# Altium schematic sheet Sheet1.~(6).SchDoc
size A3; SheetNumber: 1; SheetTotal: 1
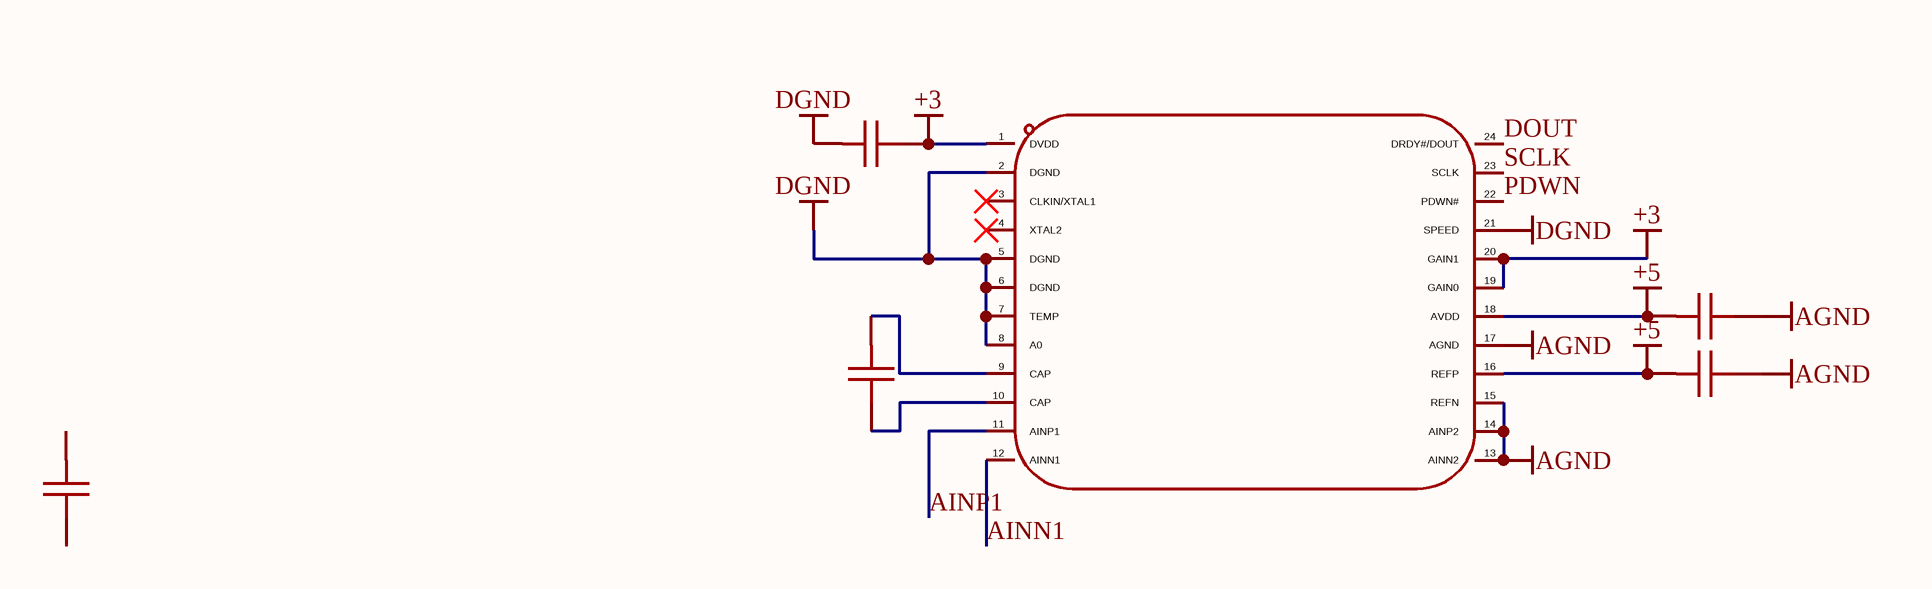
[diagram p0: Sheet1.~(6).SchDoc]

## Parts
(Parts that share a designator on the sheet are numbered #1, #2 ... from top to bottom, then left to right.)
C?#1  cga0603x7r104k500jt  [C0603]  (value not drawn)
C?#2  cga0603x7r104k500jt  [C0603]  (value not drawn)
C?#3  cga0603x7r104k500jt  [C0603]  (value not drawn)
C?#4  cga0603x7r104k500jt  [C0603]  (value not drawn)
C??  cga0603x7r104k500jt  [C0603]  (value not drawn)
U??  ads1232ipwr  [TSSOP-24_L7.8-W4.4-P0.65-LS6.4-BL]  (value not drawn)

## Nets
+3: C?#1.1 U??.1(DVDD) U??.19(GAIN0) U??.20(GAIN1)
+5: C?#2.2 C?#3.2 U??.16(REFP) U??.18(AVDD)
AGND: C?#2.1 C?#3.1 U??.13(AINN2) U??.14(AINP2) U??.15(REFN) U??.17(AGND)
DGND: C?#1.2 U??.2(DGND) U??.5(DGND) U??.6(DGND) U??.7(TEMP) U??.8(A0) U??.21(SPEED)
AINN1: U??.12(AINN1)
AINP1: U??.11(AINP1)
DOUT: U??.24(DRDY#/DOUT)
PDWN: U??.22(PDWN#)
SCLK: U??.23(SCLK)
NetC??_1: C??.1 U??.10(CAP)
NetC??_2: C??.2 U??.9(CAP)

Not connected (* = marked no-connect by the designer): C?#4 1 2; U?? 3(CLKIN/XTAL1)* 4(XTAL2)*

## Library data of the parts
C?#1-C?#4 C?? = cga0603x7r104k500jt: 容值:100nF;精度:±10%;额定电压:50V;温度系数:X7R;; Manufacturer: HRE(芯声); AddInBom: yes; ModelId: ac125912035d415993ca9572d50418b1; ModelName: C0603_L1.6-W0.8-H0.8; ModelTransform: 62.992,31.496,0,0,0,0,0,0,0; Value: 100nF; Tolerance: ±10%; Voltage Rating: 50V; Temperature Coefficient: X7R
U?? = ads1232ipwr: 分辨率(位):24;采样率:10Hz;工作电压:2.7V~5.3V;接口类型:SPI;; Manufacturer: TI(德州仪器); AddInBom: yes; ModelId: 57e278220af748a2882c4abba4094eb9; ModelName: TSSOP-24_L7.8-W4.4-H1.0-LS6.4-P0.65; ModelTransform: 252.188,307.086,0,90,0,0,0,0,0; Resolution (Bits): 24; Sampling Rate: 10Hz; number of channels: 2; Interface: SPI; differential input: 是; Clock/Oscillator: 内置；外置; Clock Frequency: 4.9152MHz；200kHz~8MHz; Voltage Reference: 外置; Programmable Gain: 支持; Temperature Sensors: 内置; ADC architecture: Sigma-Delta; Data rate: 80Hz；10Hz; Quiescent Current (Iq): 1.3uA; Full-Scale Range(FSR): 39mV；1.25V；19.5mV；2.5V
